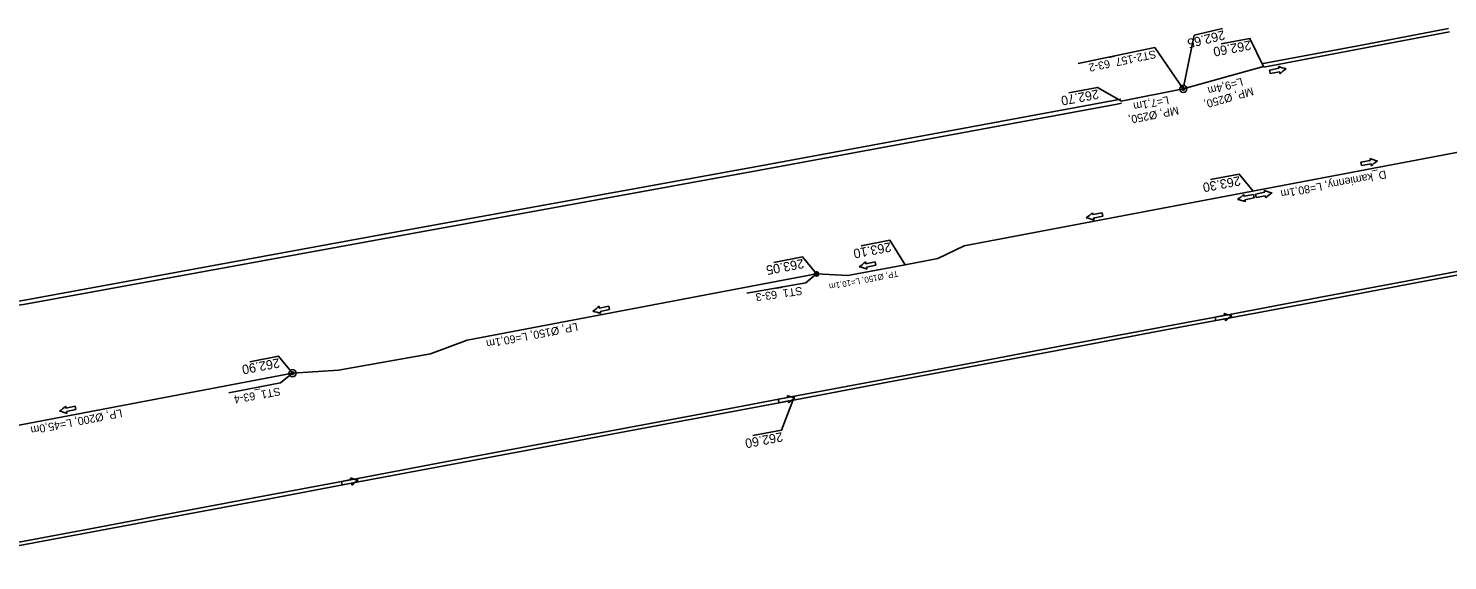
# Model space of a CAD drawing. Extents: x -1 to 65640748, y -22 to 5530284.
# Drawn here: x 6555842 to 6556001.7, y 5528361.6 to 5528421.5 of the extents above; entities that cross this region are included whole.
import ezdxf

# ---------------------------------------------------------------- set-up
doc = ezdxf.new("R2010")
doc.units = 0
for name, color, linetype in [('TOR_PROF-studnie i osadniki', 7, 'Continuous'), ('TOR_PS_ODW-drenaze', 7, 'Continuous'), ('TOR_PS_ODW-drenokolektory', 7, 'Continuous'), ('TOR_PS_ODW-studnie PEHD', 7, 'Continuous'), ('TOR_PS_OPIS_O-opisy rurociagow', 7, 'Continuous'), ('TOR_PS_OPIS_O-opisy studni', 7, 'Continuous'), ('TOR_PS_OPIS_T-INFO', 7, 'Continuous'), ('TOR_PS_T-rowy otwarte nieumocnione', 7, 'Continuous'), ('TOR_PS_T-rowy otwarte umocnione', 7, 'Continuous')]:
    doc.layers.add(name, color=color, linetype=linetype)

msp = doc.modelspace()

# ---------------------------------------------------------------- linework, layer by layer
at = {"layer": 'TOR_PROF-studnie i osadniki'}
for radius in [0.25, 0.125]:
    msp.add_circle((6555930.67, 5528393.9), radius, dxfattribs=at)
at = {"layer": 'TOR_PS_ODW-drenaze'}
for points in [[(6556019.09, 5528410.67), (6555947.27, 5528397.05), (6555944.31, 5528395.62), (6555940.65, 5528394.93)], [(6555940.65, 5528394.93), (6555934.19, 5528393.71), (6555930.67, 5528393.9)]]:
    msp.add_lwpolyline(points, dxfattribs=at)
at = {"layer": 'TOR_PS_ODW-drenokolektory'}
for points in [[(6555980.96, 5528417.24), (6555971.92, 5528414.71), (6555964.93, 5528413.32)], [(6555980.96, 5528417.24), (6555971.92, 5528414.71), (6555964.93, 5528413.32)], [(6555930.67, 5528393.9), (6555891.37, 5528386.45), (6555887.25, 5528384.91), (6555876.89, 5528383.07), (6555871.72, 5528382.73)], [(6555871.72, 5528382.73), (6555827.51, 5528374.35), (6555827.51, 5528374.35)]]:
    msp.add_lwpolyline(points, dxfattribs=at)
at = {"layer": 'TOR_PS_ODW-studnie PEHD'}
for centre, radius in [((6555971.92, 5528414.71), 0.4), ((6555971.92, 5528414.71), 0.145), ((6555930.67, 5528393.9), 0.25), ((6555930.67, 5528393.9), 0.112), ((6555871.72, 5528382.73), 0.4), ((6555871.72, 5528382.73), 0.145)]:
    msp.add_circle(centre, radius, dxfattribs=at)
at = {"layer": 'TOR_PS_OPIS_O-opisy rurociagow'}
for p, q in [((6555982.7, 5528417.03), (6555981.62, 5528416.83)), ((6555982.7, 5528417.03), (6555981.62, 5528416.83)), ((6555981.62, 5528416.83), (6555981.7, 5528416.44)), ((6555981.62, 5528416.83), (6555981.7, 5528416.44)), ((6555981.7, 5528416.44), (6555982.77, 5528416.64)), ((6555982.77, 5528416.64), (6555981.7, 5528416.44)), ((6555992.98, 5528406.67), (6555991.9, 5528406.48)), ((6555992.98, 5528406.67), (6555991.9, 5528406.48)), ((6555991.9, 5528406.48), (6555991.97, 5528406.09)), ((6555991.9, 5528406.48), (6555991.97, 5528406.09)), ((6555991.97, 5528406.09), (6555993.05, 5528406.27)), ((6555993.05, 5528406.27), (6555991.97, 5528406.09)), ((6555978.75, 5528402.63), (6555979.82, 5528402.85)), ((6555978.75, 5528402.63), (6555979.82, 5528402.85)), ((6555979.9, 5528402.46), (6555978.83, 5528402.24)), ((6555978.83, 5528402.24), (6555979.9, 5528402.46)), ((6555979.82, 5528402.85), (6555979.9, 5528402.46)), ((6555979.82, 5528402.85), (6555979.9, 5528402.46)), ((6555981.11, 5528403.08), (6555980.03, 5528402.89)), ((6555981.11, 5528403.08), (6555980.03, 5528402.89)), ((6555980.03, 5528402.89), (6555980.1, 5528402.5)), ((6555980.03, 5528402.89), (6555980.1, 5528402.5)), ((6555980.1, 5528402.5), (6555981.18, 5528402.69)), ((6555981.18, 5528402.69), (6555980.1, 5528402.5)), ((6555961.72, 5528400.57), (6555962.79, 5528400.79)), ((6555961.72, 5528400.57), (6555962.79, 5528400.79)), ((6555962.79, 5528400.79), (6555962.87, 5528400.4)), ((6555962.79, 5528400.79), (6555962.87, 5528400.4)), ((6555962.87, 5528400.4), (6555961.8, 5528400.18)), ((6555961.8, 5528400.18), (6555962.87, 5528400.4)), ((6555936.2, 5528395.05), (6555937.27, 5528395.27)), ((6555936.2, 5528395.05), (6555937.27, 5528395.27)), ((6555937.35, 5528394.88), (6555936.28, 5528394.66)), ((6555936.28, 5528394.66), (6555937.35, 5528394.88)), ((6555937.27, 5528395.27), (6555937.35, 5528394.88)), ((6555937.27, 5528395.27), (6555937.35, 5528394.88)), ((6555906.23, 5528390.05), (6555907.3, 5528390.27)), ((6555906.23, 5528390.05), (6555907.3, 5528390.27)), ((6555907.38, 5528389.88), (6555906.31, 5528389.66)), ((6555906.31, 5528389.66), (6555907.38, 5528389.88)), ((6555907.3, 5528390.27), (6555907.38, 5528389.88)), ((6555907.3, 5528390.27), (6555907.38, 5528389.88)), ((6555976.58, 5528389.25), (6555975.51, 5528389.05)), ((6555976.58, 5528389.25), (6555975.51, 5528389.05)), ((6555975.51, 5528389.05), (6555975.58, 5528388.65)), ((6555975.51, 5528389.05), (6555975.58, 5528388.65)), ((6555975.58, 5528388.65), (6555976.66, 5528388.86)), ((6555976.66, 5528388.86), (6555975.58, 5528388.65)), ((6555927.44, 5528380), (6555926.37, 5528379.8)), ((6555927.44, 5528380), (6555926.37, 5528379.8)), ((6555846.21, 5528378.81), (6555847.28, 5528379.03)), ((6555846.21, 5528378.81), (6555847.28, 5528379.03)), ((6555847.36, 5528378.64), (6555846.29, 5528378.42)), ((6555846.29, 5528378.42), (6555847.36, 5528378.64)), ((6555847.28, 5528379.03), (6555847.36, 5528378.64)), ((6555847.28, 5528379.03), (6555847.36, 5528378.64)), ((6555926.37, 5528379.8), (6555926.44, 5528379.41)), ((6555926.37, 5528379.8), (6555926.44, 5528379.41)), ((6555926.44, 5528379.41), (6555927.52, 5528379.61)), ((6555927.52, 5528379.61), (6555926.44, 5528379.41)), ((6555878.31, 5528370.76), (6555877.23, 5528370.55)), ((6555878.31, 5528370.76), (6555877.23, 5528370.55)), ((6555877.23, 5528370.55), (6555877.31, 5528370.16)), ((6555877.23, 5528370.55), (6555877.31, 5528370.16)), ((6555877.31, 5528370.16), (6555878.38, 5528370.36)), ((6555878.38, 5528370.36), (6555877.31, 5528370.16))]:
    msp.add_line(p, q, dxfattribs=at)
for points in [[(6555982.65, 5528417.25), (6555982.65, 5528417.25)], [(6555982.8, 5528416.42), (6555982.8, 5528416.42)], [(6555992.93, 5528406.89), (6555992.93, 5528406.89)], [(6555993.07, 5528406.05), (6555993.07, 5528406.05)], [(6555978.71, 5528402.85), (6555978.71, 5528402.85)], [(6555981.06, 5528403.3), (6555981.06, 5528403.3)], [(6555981.2, 5528402.46), (6555981.2, 5528402.46)], [(6555961.69, 5528400.79), (6555961.69, 5528400.79)], [(6555978.88, 5528402.02), (6555978.88, 5528402.02)], [(6555961.86, 5528399.96), (6555961.86, 5528399.96)], [(6555936.16, 5528395.27), (6555936.16, 5528395.27)], [(6555936.33, 5528394.44), (6555936.33, 5528394.44)], [(6555906.19, 5528390.27), (6555906.19, 5528390.27)], [(6555906.37, 5528389.44), (6555906.37, 5528389.44)], [(6555976.53, 5528389.47), (6555976.53, 5528389.47)], [(6555976.69, 5528388.63), (6555976.69, 5528388.63)], [(6555927.39, 5528380.22), (6555927.39, 5528380.22)], [(6555846.18, 5528379.03), (6555846.18, 5528379.03)], [(6555927.55, 5528379.39), (6555927.55, 5528379.39)], [(6555846.35, 5528378.2), (6555846.35, 5528378.2)], [(6555878.25, 5528370.97), (6555878.25, 5528370.97)], [(6555878.41, 5528370.14), (6555878.41, 5528370.14)]]:
    msp.add_lwpolyline(points, dxfattribs=at)
for centre, radius, start, end in [((6555984.57, 5528421.78), 4.92, 246.9274, 257.3092), ((6555983.1, 5528417.24), 0.458, 179.042, 207.5032), ((6555984.57, 5528421.78), 4.92, 246.9274, 257.3092), ((6555983.1, 5528417.24), 0.458, 179.042, 207.5032), ((6555986.24, 5528412.9), 4.92, 123.9653, 134.3471), ((6555986.24, 5528412.9), 4.92, 123.9653, 134.3471), ((6555983.23, 5528416.59), 0.458, 173.7713, 202.2325), ((6555983.23, 5528416.59), 0.458, 173.7713, 202.2325), ((6555994.92, 5528411.38), 4.92, 246.1449, 256.5268), ((6555993.39, 5528406.87), 0.458, 178.2595, 206.7208), ((6555994.92, 5528411.38), 4.92, 246.1449, 256.5268), ((6555993.39, 5528406.87), 0.458, 178.2595, 206.7208), ((6555993.5, 5528406.22), 0.458, 172.9889, 201.4501), ((6555993.5, 5528406.22), 0.458, 172.9889, 201.4501), ((6555996.46, 5528402.49), 4.92, 123.1828, 133.5647), ((6555996.46, 5528402.49), 4.92, 123.1828, 133.5647), ((6555975.21, 5528406.31), 4.92, 304.9397, 315.3215), ((6555975.21, 5528406.31), 4.92, 304.9397, 315.3215), ((6555978.29, 5528402.67), 0.458, 354.7457, 23.207), ((6555978.29, 5528402.67), 0.458, 354.7457, 23.207), ((6555983.05, 5528407.8), 4.92, 246.1449, 256.5268), ((6555981.52, 5528403.29), 0.458, 178.2595, 206.7208), ((6555983.05, 5528407.8), 4.92, 246.1449, 256.5268), ((6555981.52, 5528403.29), 0.458, 178.2595, 206.7208), ((6555981.63, 5528402.63), 0.458, 172.9889, 201.4501), ((6555981.63, 5528402.63), 0.458, 172.9889, 201.4501), ((6555984.59, 5528398.9), 4.92, 123.1828, 133.5647), ((6555984.59, 5528398.9), 4.92, 123.1828, 133.5647), ((6555958.19, 5528404.25), 4.92, 304.9397, 315.3215), ((6555958.19, 5528404.25), 4.92, 304.9397, 315.3215), ((6555961.27, 5528400.61), 0.458, 354.7457, 23.207), ((6555961.27, 5528400.61), 0.458, 354.7457, 23.207), ((6555977.03, 5528397.47), 4.92, 67.9018, 78.2836), ((6555977.03, 5528397.47), 4.92, 67.9018, 78.2836), ((6555978.42, 5528402.02), 0.458, 0.0164, 28.4776), ((6555978.42, 5528402.02), 0.458, 0.0164, 28.4776), ((6555960.01, 5528395.4), 4.92, 67.9018, 78.2836), ((6555960.01, 5528395.4), 4.92, 67.9018, 78.2836), ((6555961.4, 5528399.96), 0.458, 0.0164, 28.4776), ((6555961.4, 5528399.96), 0.458, 0.0164, 28.4776), ((6555932.66, 5528398.73), 4.92, 304.9397, 315.3215), ((6555932.66, 5528398.73), 4.92, 304.9397, 315.3215), ((6555934.48, 5528389.89), 4.92, 67.9018, 78.2836), ((6555934.48, 5528389.89), 4.92, 67.9018, 78.2836), ((6555935.74, 5528395.09), 0.458, 354.7457, 23.207), ((6555935.74, 5528395.09), 0.458, 354.7457, 23.207), ((6555935.87, 5528394.44), 0.458, 0.0164, 28.4776), ((6555935.87, 5528394.44), 0.458, 0.0164, 28.4776), ((6555902.7, 5528393.73), 4.92, 304.9397, 315.3215), ((6555902.7, 5528393.73), 4.92, 304.9397, 315.3215), ((6555904.52, 5528384.88), 4.92, 67.9018, 78.2836), ((6555904.52, 5528384.88), 4.92, 67.9018, 78.2836), ((6555905.77, 5528390.09), 0.458, 354.7457, 23.207), ((6555905.77, 5528390.09), 0.458, 354.7457, 23.207), ((6555905.91, 5528389.44), 0.458, 0.0164, 28.4776), ((6555905.91, 5528389.44), 0.458, 0.0164, 28.4776), ((6555978.46, 5528393.99), 4.92, 246.945, 257.3268), ((6555976.99, 5528389.46), 0.458, 179.0596, 207.5208), ((6555978.46, 5528393.99), 4.92, 246.945, 257.3268), ((6555976.99, 5528389.46), 0.458, 179.0596, 207.5208), ((6555977.11, 5528388.81), 0.458, 173.7889, 202.2502), ((6555977.11, 5528388.81), 0.458, 173.7889, 202.2502), ((6555980.13, 5528385.12), 4.92, 123.9829, 134.3647), ((6555980.13, 5528385.12), 4.92, 123.9829, 134.3647), ((6555929.32, 5528384.75), 4.92, 246.9517, 257.3335), ((6555927.85, 5528380.21), 0.458, 179.0663, 207.5275), ((6555929.32, 5528384.75), 4.92, 246.9517, 257.3335), ((6555927.85, 5528380.21), 0.458, 179.0663, 207.5275), ((6555842.68, 5528382.49), 4.92, 304.9397, 315.3215), ((6555842.68, 5528382.49), 4.92, 304.9397, 315.3215), ((6555844.5, 5528373.64), 4.92, 67.9018, 78.2836), ((6555844.5, 5528373.64), 4.92, 67.9018, 78.2836), ((6555845.76, 5528378.85), 0.458, 354.7457, 23.207), ((6555845.76, 5528378.85), 0.458, 354.7457, 23.207), ((6555845.89, 5528378.2), 0.458, 0.0164, 28.4776), ((6555845.89, 5528378.2), 0.458, 0.0164, 28.4776), ((6555927.97, 5528379.56), 0.458, 173.7956, 202.2568), ((6555927.97, 5528379.56), 0.458, 173.7956, 202.2568), ((6555930.99, 5528375.87), 4.92, 123.9896, 134.3714), ((6555930.99, 5528375.87), 4.92, 123.9896, 134.3714), ((6555880.18, 5528375.5), 4.92, 246.9506, 257.3325), ((6555880.18, 5528375.5), 4.92, 246.9506, 257.3325), ((6555878.71, 5528370.97), 0.458, 179.0652, 207.5264), ((6555878.71, 5528370.97), 0.458, 179.0652, 207.5264), ((6555881.85, 5528366.62), 4.92, 123.9885, 134.3703), ((6555881.85, 5528366.62), 4.92, 123.9885, 134.3703), ((6555878.84, 5528370.31), 0.458, 173.7945, 202.2558), ((6555878.84, 5528370.31), 0.458, 173.7945, 202.2558)]:
    msp.add_arc(centre, radius, start, end, dxfattribs=at)
at = {"layer": 'TOR_PS_OPIS_T-INFO'}
for points in [[(6555971.92, 5528414.71), (6555973.15, 5528420.74), (6555976.34, 5528421.52)], [(6555980.96, 5528417.24), (6555979.41, 5528420.39), (6555976.17, 5528419.77)], [(6555971.92, 5528414.71), (6555968.71, 5528419.36), (6555960.1, 5528417.58)], [(6555964.96, 5528413.33), (6555962.27, 5528414.89), (6555959.04, 5528414.27)], [(6555979.79, 5528403.22), (6555978.22, 5528405.13), (6555974.99, 5528404.51)], [(6555940.65, 5528394.93), (6555938.92, 5528397.68), (6555935.69, 5528397.06)], [(6555930.67, 5528393.9), (6555929.1, 5528395.82), (6555925.86, 5528395.2)], [(6555930.67, 5528393.9), (6555929.45, 5528392.88), (6555922.84, 5528391.75)], [(6555871.72, 5528382.73), (6555870.14, 5528384.65), (6555866.91, 5528384.02)], [(6555871.72, 5528382.73), (6555870.38, 5528381.65), (6555864.55, 5528380.52)], [(6555928.19, 5528380.14), (6555926.73, 5528376.34), (6555923.5, 5528375.71)]]:
    msp.add_lwpolyline(points, dxfattribs=at)
at = {"layer": 'TOR_PS_T-rowy otwarte nieumocnione'}
for points in [[(6555825.88, 5528388.85), (6555841.38, 5528390.92), (6555883.85, 5528398.71), (6555924.19, 5528406.04), (6555964.88, 5528413.56)], [(6555825.94, 5528388.38), (6555841.45, 5528390.45), (6555883.94, 5528398.24), (6555924.27, 5528405.57), (6555964.49, 5528413.01), (6555964.97, 5528413.1)]]:
    msp.add_lwpolyline(points, dxfattribs=at)
at = {"layer": 'TOR_PS_T-rowy otwarte umocnione'}
for points in [[(6556001.77, 5528421.51), (6555991.95, 5528419.65), (6555980.9, 5528417.56)], [(6556001.85, 5528421.12), (6555992.02, 5528419.26), (6555980.97, 5528417.17)], [(6556006.81, 5528394.95), (6555996.98, 5528393.09), (6555987.15, 5528391.24), (6555977.33, 5528389.39), (6555971.28, 5528388.25), (6555971.27, 5528388.25), (6555967.5, 5528387.54), (6555957.67, 5528385.69), (6555947.84, 5528383.84), (6555938.02, 5528381.99), (6555928.19, 5528380.14), (6555918.36, 5528378.29), (6555908.53, 5528376.44), (6555898.71, 5528374.6), (6555888.88, 5528372.75), (6555879.05, 5528370.9), (6555869.22, 5528369.05), (6555859.4, 5528367.2), (6555849.57, 5528365.35), (6555839.74, 5528363.5), (6555829.91, 5528361.65)], [(6556006.88, 5528394.56), (6555997.06, 5528392.7), (6555987.23, 5528390.85), (6555977.4, 5528389), (6555971.36, 5528387.86), (6555971.35, 5528387.86), (6555967.57, 5528387.15), (6555957.75, 5528385.3), (6555947.92, 5528383.45), (6555938.09, 5528381.6), (6555928.26, 5528379.75), (6555918.44, 5528377.9), (6555908.61, 5528376.05), (6555898.78, 5528374.2), (6555888.95, 5528372.35), (6555879.13, 5528370.5), (6555869.3, 5528368.65), (6555859.47, 5528366.8), (6555849.64, 5528364.96), (6555839.82, 5528363.11)]]:
    msp.add_lwpolyline(points, dxfattribs=at)

# ---------------------------------------------------------------- texts
at = {"layer": 'TOR_PS_OPIS_O-opisy rurociagow'}
for s, height, rotation, p in [('L=9,4m', 0.9, 195.6447, (6555978.48, 5528415.98)), ('L=7,1m', 0.9, 190.9157, (6555970.21, 5528413.91)), ('MP, Ø250, ', 0.9, 195.6447, (6555979.68, 5528414.91)), ('MP, Ø250, ', 0.9, 190.9157, (6555971.32, 5528412.75)), ('D_kamienny, L=80,1m', 0.9, 190.7332, (6555994.67, 5528405.55)), ('TP, Ø150, L=10,1m', 0.675, 190.9157, (6555939.78, 5528394.27)), ('LP, Ø150, L=60,1m', 0.9, 190.9157, (6555903.72, 5528388.41)), ('LP, Ø200, L=45,0m', 0.9, 190.9157, (6555852.47, 5528378.7))]:
    msp.add_text(s, height=height, rotation=rotation, dxfattribs=at).set_placement(p)
at = {"layer": 'TOR_PS_OPIS_O-opisy studni'}
for s, rotation, p in [('ST2-157_63-2', 191.7584, (6555968.75, 5528419.08)), ('ST1_63-3', 188.3677, (6555929, 5528392.46)), ('ST1_63-4', 190.2815, (6555870.27, 5528381.14))]:
    msp.add_text(s, height=0.9, rotation=rotation, dxfattribs=at).set_placement(p)
at = {"layer": 'TOR_PS_OPIS_T-INFO'}
for s, rotation, p in [('262.65', 193.9052, (6555976.46, 5528421.32)), ('262.60', 190.7159, (6555979.44, 5528420.17)), ('262.70', 190.7159, (6555962.31, 5528414.66)), ('263.30', 190.7159, (6555978.26, 5528404.91)), ('263.10', 190.7159, (6555938.96, 5528397.46)), ('263.05', 190.7159, (6555929.14, 5528395.6)), ('262.90', 190.7159, (6555870.18, 5528384.42)), ('262.60', 190.7159, (6555926.77, 5528376.11))]:
    msp.add_text(s, height=1.05, rotation=rotation, dxfattribs=at).set_placement(p)

doc.saveas('drawing.dxf')
